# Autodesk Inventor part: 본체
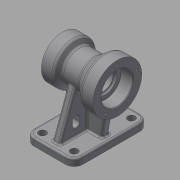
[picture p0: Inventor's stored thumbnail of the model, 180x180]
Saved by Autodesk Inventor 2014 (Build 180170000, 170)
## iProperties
Created: 2015-08
Part Number: 본체
Material: 일반
Document SubType Name: Modeling
Designer: USER
Density: 1 g/cm^3
Appearance: 기본값
Mass: 392.172 g
Surface Area: 749.652 cm^2
Volume: 392.172 cm^3
Author: USER
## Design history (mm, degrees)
sketch "스케치1"
  geometry: L1 (-40, -61)-(40, -61); L2 (40, -61)-(40, 61); L3 (40, 61)-(-40, 61); L4 (-40, 61)-(-40, -61); 3 further points
  constraints: 8 end point, 2 midpoint, 2 parallel, 1 horizontal, 1 horizontal alignment, 1 perpendicular, 1 vertical alignment
  dimensions: "d0" = 122 distance of L3.end L1.start; "d1" = 80 distance of L1.start L1.end
extrude "돌출1" new body sketch "스케치1" distance "d2" = 12; taper "d3" = 0 deg
sketch "스케치2"
  geometry: L1 (40, 0)-(-40, 0) reference; L2 (-40, 0)-(-40, 12) reference; L3 (40, 12)-(-40, 12) reference; L4 (40, 0)-(40, 12) reference; L5 (-50, 90)-(-50, 130); L6 (-50, 130)-(-30, 130); L7 (-30, 130)-(-13.315, 116); L8 (-13.315, 116)-(14.804, 116); L9 (14.804, 116)-(20, 125); L10 (20, 125)-(40, 125); L11 (40, 125)-(40, 90); L12 (-50, 90)-(40, 90); 1 further point
  constraints: 16 end point, 5 parallel, 2 perpendicular, 1 midpoint, 1 vertical alignment
  dimensions: "d4" = 90 distance between parallel lines of L11 L5; "d5" = 20 distance of L5.end L6.end; "d6" = 20 distance of L9.end L10.end; "d7" = 40 deg angle of L8 L7; "d8" = 60 deg angle of L9 L8; "d15" = 70 diameter of L10 L12; "d16" = 80 diameter of L6 L12; "d17" = 90 distance between parallel lines of L1 L12; "d18" = 52 diameter of L8 L12
revolve "회전1" sketch "스케치2" stored, may be unused: angle "d19" = 90 deg
sketch "스케치3"
  geometry: L1 (61, 12)-(-61, 12) reference; L2 (61, 0)-(61, 12) reference; L3 (-61, 0)-(-61, 12) reference; L4 (-51, 12)-(-29.478, 71.131); L5 (51, 12)-(29.478, 71.131); L6 (-29.478, 71.131)-(-25.091, 83.185); L7 (29.478, 71.131)-(25.091, 83.185); A1 r 35 centre (0, 90) between (-29.478, 71.131) and (29.478, 71.131) reference; A2 r 26 centre (0, 90) between (-25.091, 83.185) and (25.091, 83.185) reference; 1 further point
  constraints: 8 end point, 4 point on circle, 2 collinear, 2 point on line
  dimensions: "d22" = 10 distance from line of L2 L5.start; "d23" = 10 distance from line of L3 L4.start; "d24" = 70 deg angle of L1 L4; "d25" = 70 deg angle of L1 L5
extrude "돌출2" join sketch "스케치3" stored distance "d26" = 12; taper "d27" = 0 deg
sketch "스케치4"
  geometry: L1 (-50, 50)-(-50, 130) reference; L2 (-30, 50)-(-30, 130) reference; L3 (-30, 50)-(-30, 130) reference; L4 (-13.315, 64)-(-13.315, 116) reference; L5 (6, 83.185)-(6, 83.185) reference; L6 (6, 83.185)-(-6, 83.185) reference; L7 (-6, 83.185)-(-6, 83.185) reference; L8 (-6, 83.185)-(6, 83.185) reference; L9 (-13.315, 64)-(-13.315, 116) reference; L10 (14.804, 64)-(14.804, 116) reference; L11 (20, 55)-(20, 125) reference; L12 (40, 55)-(40, 125) reference; L13 (-6, 83.185)-(-6, 12) reference; L14 (6, 83.185)-(-6, 83.185) reference; L15 (6, 12)-(6, 83.185) reference; L16 (-6, 12)-(6, 12) reference; L17 (40, 0)-(-40, 0) reference; L18 (-40, 0)-(-40, 12) reference; L19 (40, 12)-(-40, 12) reference; L20 (40, 0)-(40, 12) reference; L21 (-30, 12)-(-36.7, 50); L22 (-50, 50)-(-30, 50) reference; 1 further point
  constraints: 2 end point, 2 point on line
  dimensions: "d28" = 80 deg angle of L19 L21; "d29" = 10 distance of L21.start L18.end
feature "리브1" sketch "스케치4" dims "d30" = 1, "d31" = 12, "d32" = 0, "d33" = 0, "d34" = 1, "d35" = 1
sketch "스케치5"
  geometry: L1 (-40, 0)-(40, 0) reference; L2 (40, 0)-(40, 12) reference; L3 (-40, 12)-(40, 12) reference; L4 (-40, 0)-(-40, 12) reference; L5 (20, 55)-(20, 125) reference; L6 (40, 55)-(40, 125) reference; L7 (30, 12)-(30, 55); L8 (20, 55)-(40, 55) reference; 1 further point
  constraints: 2 end point, 1 midpoint, 1 parallel, 1 point on line
  dimensions: "d36" = 10 distance between parallel lines of L2 L7
feature "리브2" sketch "스케치5" dims "d37" = 1, "d38" = 12, "d39" = 0, "d40" = 0, "d41" = 1, "d42" = 1
sketch "스케치6"
  geometry: L1 (-12, -6)-(-64.702, -6) reference; L2 (-30, -24)-(-36, -24); L3 (-30, -30)-(-36, -30); L4 (-36, -18)-(-30, -18); L5 (-30, 24)-(-36, 24); L6 (-30, 18)-(-36, 18); L7 (-36, 30)-(-30, 30); L8 (0, 61)-(0, -61) reference; L9 (-33, -24)-(-33, 24); A1 r 6 centre (-30, -24) between (-30, -30) and (-30, -18); A2 r 6 centre (-36, -24) between (-36, -18) and (-36, -30); A3 r 6 centre (-30, 24) between (-30, 18) and (-30, 30); A4 r 6 centre (-36, 24) between (-36, 30) and (-36, 18); 3 further points
  constraints: 18 end point, 8 point on circle, 8 tangent, 5 parallel, 4 centre point, 4 midpoint, 1 horizontal alignment, 1 vertical alignment
  dimensions: "d43" = 12 distance between parallel lines of L3 L4; "d44" = 18 dimension on A1 A2; "d45" = 12 distance between parallel lines of L6 L7; "d46" = 18 dimension on A3 A4; "d47" = 48 distance from line of L5 L2.start; "d48" = 30 distance from line of L8 L3.start
extrude "돌출3" cut sketch "스케치6" distance "d49" = 12; taper "d50" = 0 deg
fillet "모깎기1" dims "d51" = 14
sketch "스케치7"
  geometry: A1 r 14 centre (-26, 47) between (-26, 61) and (-40, 47) reference; A2 r 14 centre (-26, -47) between (-40, -47) and (-26, -61) reference; A3 r 14 centre (26, -47) between (26, -61) and (40, -47) reference; A4 r 14 centre (26, 47) between (40, 47) and (26, 61) reference; 5 further points
  constraints: 4 coincident
hole "구멍1" sketch "스케치7" at (-26, 47), (26, 47), (26, -47), (-26, -47) diameter "d52" = 12; stored, may be unused: countersink angle "d56" = 90 deg, drill point angle "d58" = 118 deg; dims "d53" = 6, "d54" = 4, "d55" = 2, "d57" = 20
fillet "모깎기2" dims "d59" = 3
sketch "스케치8"
  geometry: C1 r 40 at (0, 0) reference; 2 further points
  constraints: 1 coincident
hole "구멍2" sketch "스케치8" at (0, 0) diameter "d62" = 32; stored, may be unused: countersink angle "d66" = 90 deg, drill point angle "d68" = 118 deg; dims "d63" = 6, "d64" = 52, "d65" = 20, "d67" = 50
sketch "스케치9"
  geometry: C1 r 35 at (0, 0) reference; 2 further points
  constraints: 1 coincident
hole "구멍3" sketch "스케치9" at (0, 0) diameter "d69" = 32; stored, may be unused: countersink angle "d73" = 90 deg, drill point angle "d75" = 118 deg; dims "d70" = 6, "d71" = 40, "d72" = 17, "d74" = 50
sketch "스케치10" dims "d76" = 54
  geometry: C1 r 20 at (0, 0) reference; C2 r 35 at (0, 0) reference; 3 further points
  constraints: 2 horizontal alignment, 1 coincident, 2 other
hole "구멍4" sketch "스케치10" at (27, 0) diameter "d77" = 3.242; stored, may be unused: countersink angle "d81" = 90 deg, drill point angle "d83" = 118 deg; dims "d78" = 10, "d79" = 40, "d80" = 17, "d82" = 13
sketch "스케치11" dims "d87" = 66
  geometry: C1 r 26 at (0, 0) reference; C2 r 40 at (0, 0) reference; 3 further points
  constraints: 2 horizontal alignment, 1 coincident, 2 other
hole "구멍5" sketch "스케치11" at (-33, 0) diameter "d88" = 3.242; stored, may be unused: countersink angle "d92" = 90 deg, drill point angle "d94" = 118 deg; dims "d89" = 10, "d90" = 40, "d91" = 17, "d93" = 13
sketch "스케치12"
  geometry: L1 (-10, 0)-(1, 0) reference; L2 (-3, 43.129)-(-3, 0) reference; 3 further points
  constraints: 1 other
  dimensions: "d98" = 24 distance from line of L1 point (13, 24); "d99" = 16 distance from line of L2 point (13, 24)
feature "엠보싱1" sketch "스케치12" dims "d0" = 122, "d1" = 80, "d18" = 52, "d100" = 0.5, "d101" = 0
fillet "모깎기5" dims "d102" = 5
fillet "모깎기6" dims "d103" = 3
sketch "스케치13"
  geometry: C1 r 40 at (0, 0) reference; 2 further points
  constraints: 1 coincident
hole "구멍6" sketch "스케치13" at (0, 0) diameter "d104" = 38; stored, may be unused: countersink angle "d108" = 90 deg, drill point angle "d110" = 0 deg; dims "d105" = 10, "d106" = 40, "d107" = 17, "d109" = 23
fillet "모깎기7" dims "d111" = 3
fillet "모깎기8" dims "d112" = 0.3
chamfer "모따기1" distance "d113" = 1; stored, may be unused: second distance "d114" = 2, angle "d115" = 45 deg
fillet "모깎기9" dims "d116" = 3
node "솔리드1"
pattern_circular "원형 패턴1" dims angle "d85" = 360 deg
pattern_circular "원형 패턴2" dims angle "d96" = 360 deg
node "투영된 루프1"
node "투영된 루프2"
node "투영된 루프3"
node "투영된 루프4"
node "투영된 루프5"
node "투영된 루프6"
node "투영된 루프7"
node "투영된 루프8"
node "투영된 루프9"
node "투영된 루프10"
other parameters: "d20" = 70 deg, "d21" = 70 deg
